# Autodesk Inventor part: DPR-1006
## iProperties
Created: 2004-11
Part Number: DPR-1006
Cost Center: 0 lbmass
Document SubType Name: Modeling
Designer: busseym
Manufacturer: Standard
Standards Organization: Custom
Stock Number: DPR-1006
Density: 1 g/cm^3
CAGE: 1LJX3
Dept. ID: Product Design
Description #2: ---
Finish #1: ---
Finish #2: ---
Material ID: ---
Project Number: ---
Author: busseym
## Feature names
1. Extrusion1
